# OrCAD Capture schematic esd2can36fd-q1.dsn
size A
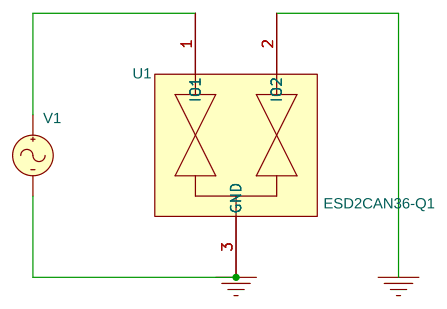
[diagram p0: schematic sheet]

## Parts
U1  ESD2CAN36-Q1
V1  VAC

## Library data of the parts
U1 = ESD2CAN36-Q1
V1 = VAC

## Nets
0: U1.2(IO2) U1.3(GND) V1.2(-)
N01783: U1.1(IO1) V1.1(+)
